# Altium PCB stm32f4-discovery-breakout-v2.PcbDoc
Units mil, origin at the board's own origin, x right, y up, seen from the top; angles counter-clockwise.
Board outline 1145.85 x 2951.23 mil, 2 copper layers (Top, Bottom); 5 components, 85 nets, 200 pads, 0 vias.
Unrouted connection lines stored in the file: 3.
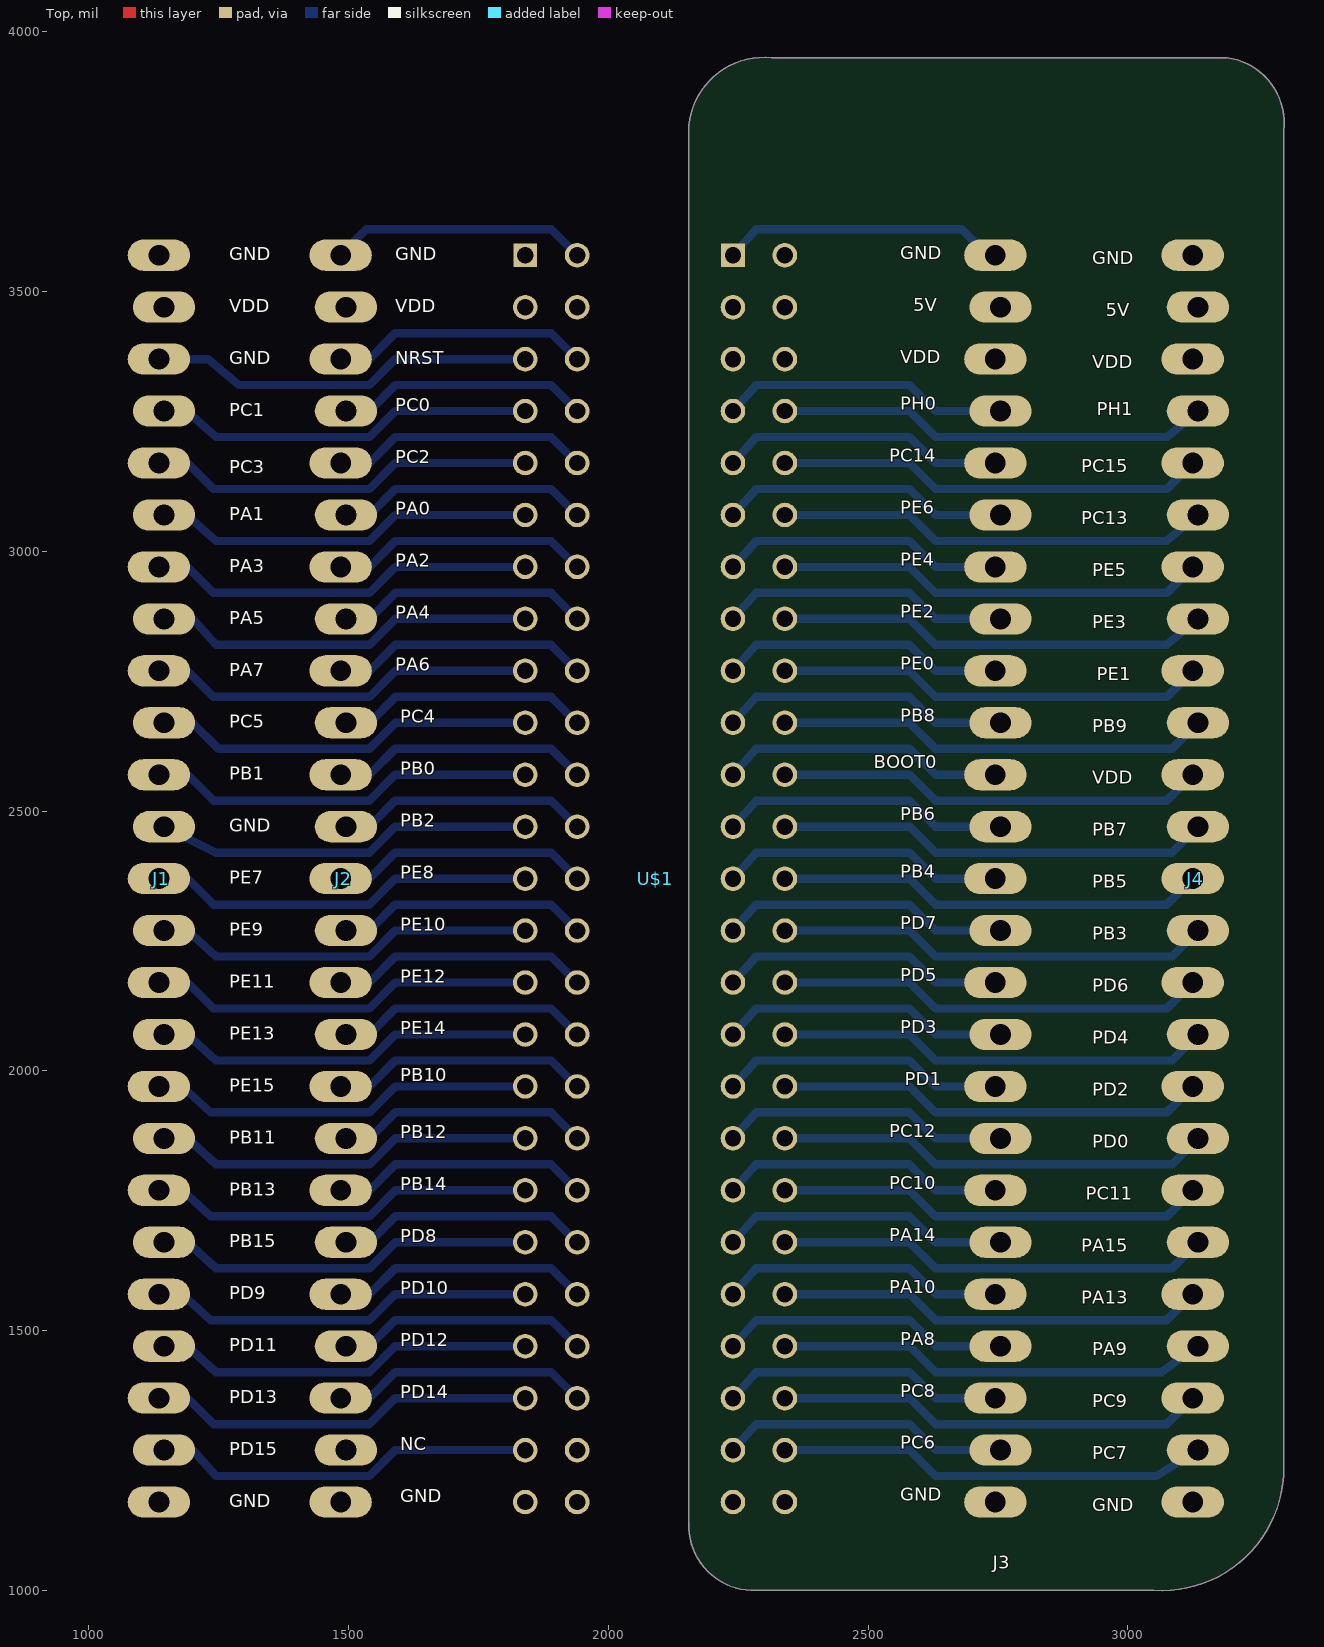
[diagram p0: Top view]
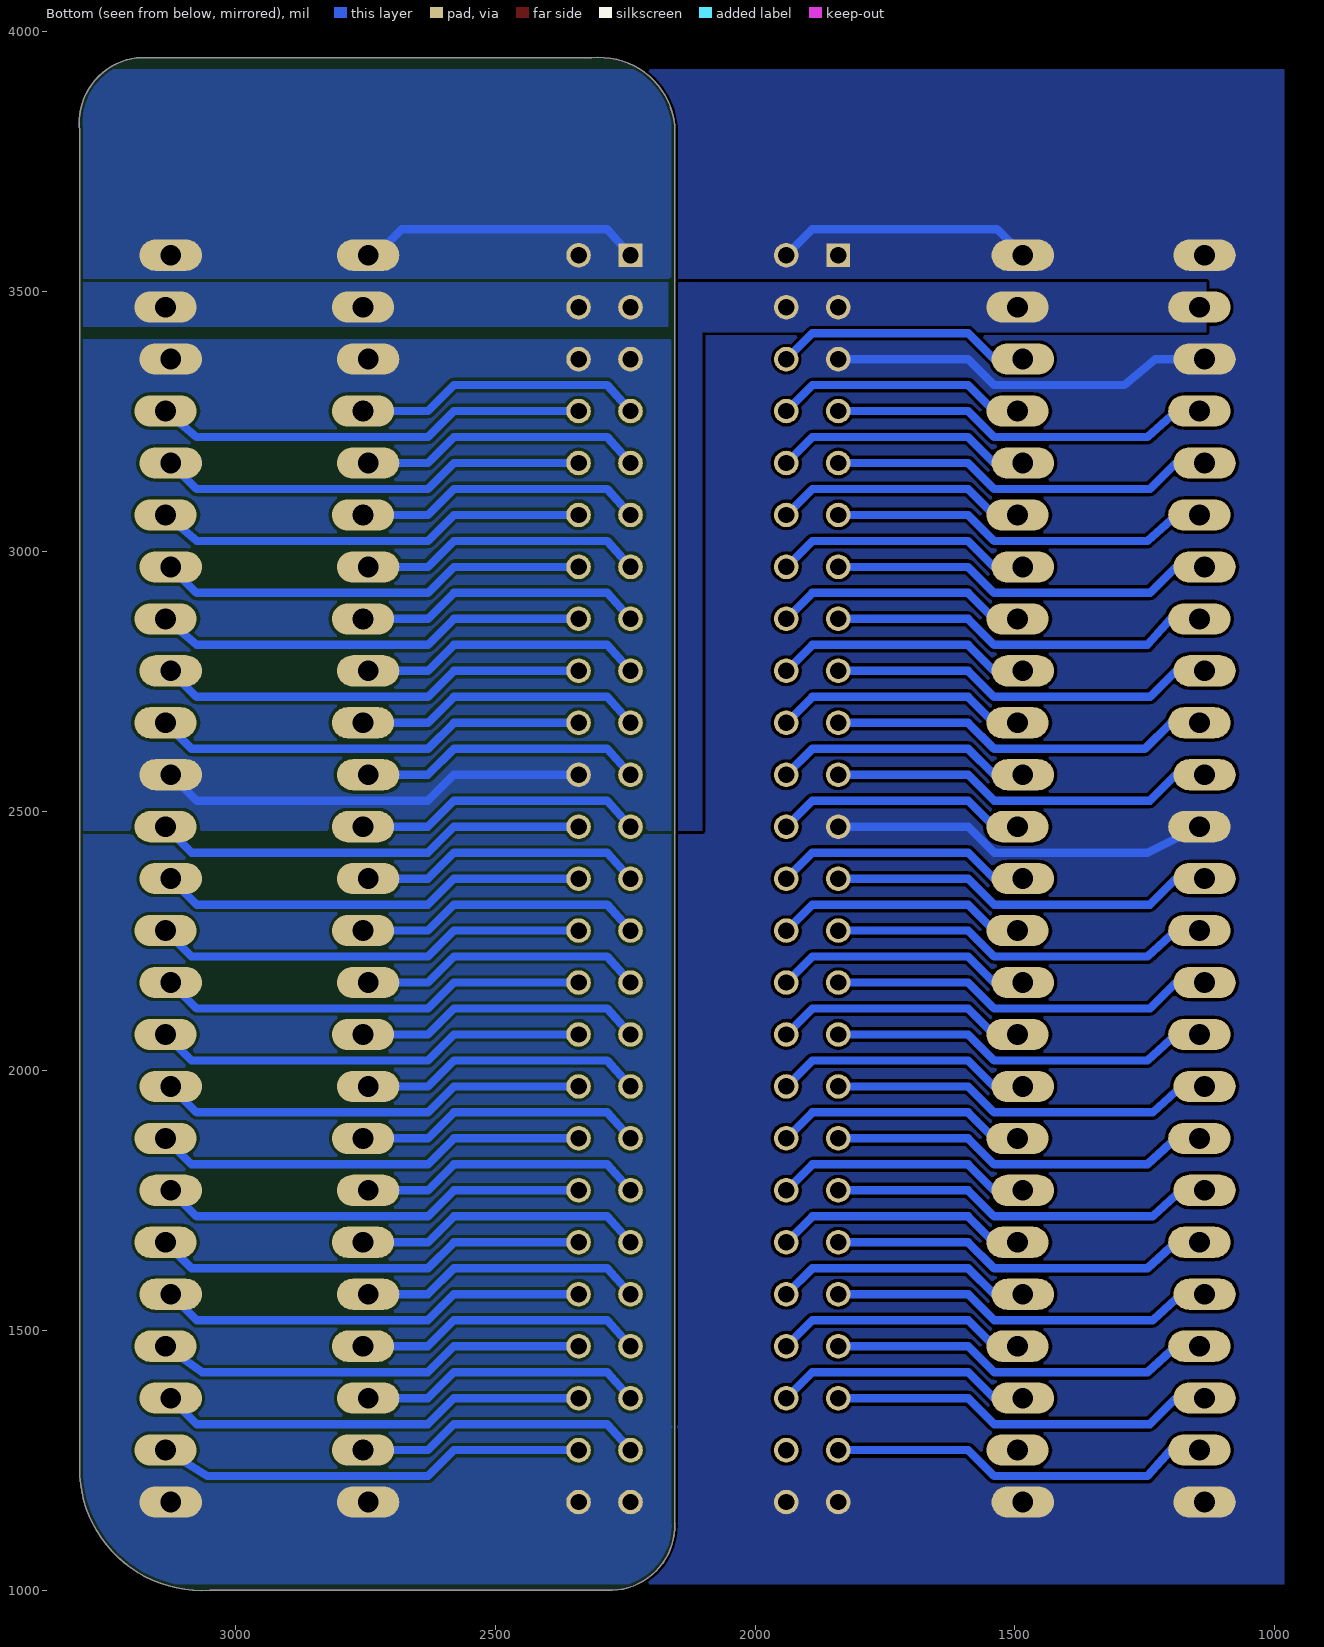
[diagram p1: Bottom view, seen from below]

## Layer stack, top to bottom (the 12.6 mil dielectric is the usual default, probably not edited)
Top Solder: solder mask 0.4, Solder Resist, Dk 3.5
Top: signal copper 1.4016
Dielectric 1: dielectric 12.6, FR-4, Dk 4.8
Bottom: signal copper 1.4016
Bottom Solder: solder mask 0.4, Solder Resist, Dk 3.5

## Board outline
2155,1320 2155,3820 cw(c2300,3805) 2315,3950 3190,3950 cw(c3175,3825) 3300,3810 3300,1220 cw(c3065,1235) 3050,1000 2275,1000 cw(c2280,1125) 2155,1130

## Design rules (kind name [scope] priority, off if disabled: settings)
Clearance "Clearance (Same Net)" [All] p1: gap=6 ignorepadtopadclearanceinfootprint=FALSE
Clearance [All] p2: gap=6 ignorepadtopadclearanceinfootprint=FALSE except(20: Arc-Poly Track-Poly SMDPad-Poly THPad-Poly Via-Poly Fill-Poly Poly-Poly Poly-Region Poly-Text Poly-Hole)
HoleSize [All] p1: absolutevalues=TRUE maxlimit=100000 minlimit=13 maxpercent=80.000 minpercent=20.000
HoleToHoleClearance mdDrill [All] p1: gap=6 allowstackedmicrovias=TRUE
PasteMaskExpansion mlMinCreamFrame [All] p1: expansion=0
PolygonConnect ThermalVias [IsVia] p1: connectstyle=Direct reliefconductorwidth=10 reliefentries=4 polygonreliefangle="90 Angle" airgapwidth=10
PolygonConnect [All] p2: connectstyle=Direct reliefconductorwidth=10 reliefentries=4 polygonreliefangle="90 Angle" airgapwidth=10
RoutingVias [All] p1: holewidth=13 width=27 viastyle="Through Hole" minholewidth=13 minwidth=27 maxholewidth=100 maxwidth=100
SolderMaskExpansion mlMinStopFrame [All] p1: expansion=3
Width [All] p1: maxlimit=10000 minlimit=6 preferedwidth=6
27 further rules are at their usual default settings.

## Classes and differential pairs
polygon class Isolate_20: Polygon_1_Net_GND Polygon_1_Net_VDD

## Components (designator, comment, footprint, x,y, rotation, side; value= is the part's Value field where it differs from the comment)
J1 "" 1X25_LOCK_LONGPADS 1140,1170 r90 top
J2 "" 1X25_LOCK_LONGPADS 1490,1170 r90 top
J3 "" 1X25_LOCK_LONGPADS 2750,1170 r90 top
J4 "" 1X25_LOCK_LONGPADS 3130,1170 r90 top
U$1 "" STM32F4-DISCOVERY 2940,2370 r0 top

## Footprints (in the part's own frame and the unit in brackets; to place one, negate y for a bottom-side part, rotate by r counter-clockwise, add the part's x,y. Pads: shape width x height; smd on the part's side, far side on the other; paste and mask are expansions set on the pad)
1X25_LOCK_LONGPADS [mil] "1X25_LOCK_LONGPADS"
  oval 60x120 / inner round 60 / far side oval 60x120 hole 40: 1(0,5) 2(100,-5) 3(200,5) 4(300,-5) 5(400,5) 6(500,-5) 7(600,5) 8(700,-5) 9(800,5) 10(900,-5) 11(1000,5) 12(1100,-5) 13(1200,5) 14(1300,-5) 15(1400,5) 16(1500,-5) 17(1600,5) 18(1700,-5) 19(1800,5) 20(1900,-5) 21(2000,5) 22(2100,-5) 23(2200,5) 24(2300,-5) 25(2400,5)
STM32F4-DISCOVERY [mil] "STM32F4-DISCOVERY"
  rect 45.75x45.75 / inner rect 60x60 / far side rect 45.75x45.75 hole 31.5: P$1(-1100,1200) P$51(-700,1200)
  round 47.25 / inner round 60 / far side round 47.25 hole 31.5: P$2(-1000,1200) P$3(-1100,1100) P$4(-1000,1100) P$5(-1100,1000) P$6(-1000,1000) P$7(-1100,900) P$8(-1000,900) P$9(-1100,800) P$10(-1000,800) P$11(-1100,700) P$12(-1000,700) P$13(-1100,600) P$14(-1000,600) P$15(-1100,500) P$16(-1000,500) P$17(-1100,400) P$18(-1000,400) P$19(-1100,300) P$20(-1000,300) P$21(-1100,200) P$22(-1000,200) P$23(-1100,100) P$24(-1000,100) P$25(-1100,0) P$26(-1000,0) P$27(-1100,-100) P$28(-1000,-100) P$29(-1100,-200) P$30(-1000,-200) P$31(-1100,-300) P$32(-1000,-300) P$33(-1100,-400) P$34(-1000,-400) P$35(-1100,-500) P$36(-1000,-500) P$37(-1100,-600) P$38(-1000,-600) P$39(-1100,-700) P$40(-1000,-700) P$41(-1100,-800) P$42(-1000,-800) P$43(-1100,-900) P$44(-1000,-900) P$45(-1100,-1000) P$46(-1000,-1000) P$47(-1100,-1100) P$48(-1000,-1100) P$49(-1100,-1200) P$50(-1000,-1200) P$52(-600,1200) P$53(-700,1100) P$54(-600,1100) P$55(-700,1000) P$56(-600,1000) P$57(-700,900) P$58(-600,900) P$59(-700,800) P$60(-600,800) P$61(-700,700) P$62(-600,700) P$63(-700,600) P$64(-600,600) P$65(-700,500) P$66(-600,500) P$67(-700,400) P$68(-600,400) P$69(-700,300) P$70(-600,300) P$71(-700,200) P$72(-600,200) P$73(-700,100) P$74(-600,100) P$75(-700,0) P$76(-600,0) P$77(-700,-100) P$78(-600,-100) P$79(-700,-200) P$80(-600,-200) P$81(-700,-300) P$82(-600,-300) P$83(-700,-400) P$84(-600,-400) P$85(-700,-500) P$86(-600,-500) P$87(-700,-600) P$88(-600,-600) P$89(-700,-700) P$90(-600,-700) P$91(-700,-800) P$92(-600,-800) P$93(-700,-900) P$94(-600,-900) P$95(-700,-1000) P$96(-600,-1000) P$97(-700,-1100) P$98(-600,-1100) P$99(-700,-1200) P$100(-600,-1200)

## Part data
J1 J2 J3 J4: library part 1X25_LOCK_LONGPADS
U$1: library part STM32F4-DISCOVERY

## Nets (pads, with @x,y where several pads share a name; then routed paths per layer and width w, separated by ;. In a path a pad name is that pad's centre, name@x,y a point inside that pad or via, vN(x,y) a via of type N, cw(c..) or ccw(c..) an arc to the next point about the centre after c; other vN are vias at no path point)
5V: J3.24 J4.24 U$1.P$53 U$1.P$54
BOOT0: J3.15 U$1.P$71 | length 548
  Bottom w16: U$1.P$71 2285,2620 2580,2620 2630,2570 J3.15
GND: J1.1 J1.14 J1.23 J1.25 J2.1 J2.25 J3.1 J3.25 J4.1 J4.25 U$1.P$1 U$1.P$2 U$1.P$5 U$1.P$23 U$1.P$49 U$1.P$50 U$1.P$51 U$1.P$52 U$1.P$99 U$1.P$100 | length 2515.7
  Bottom w16: J1.23 1230,3370 1290,3320 1540,3320 1590,3370 U$1.P$5 ; J1.14 1245,2420 1540,2420 1590,2470 U$1.P$23 ; J2.25 1535,3620 1890,3620 U$1.P$2 ; U$1.P$51 2285,3620 2680,3620 2730,3570 J3.25
NRST: J2.23 U$1.P$6 | length 496.4
  Bottom w16: J2.23 1540,3370 1590,3420 1890,3420 U$1.P$6
PA0: J2.20 U$1.P$12 | length 491.4
  Bottom w16: J2.20@1490,3070 J2.20 1540,3070 1590,3120 1890,3120 U$1.P$12
PA1: J1.20 U$1.P$11 | length 735.1
  Bottom w16: J1.20 1190,3070 1200,3060 1245,3020 1540,3020 1590,3070 U$1.P$11
PA2: J2.19 U$1.P$14 | length 496.4
  Bottom w16: J2.19 1540,2970 1590,3020 1890,3020 U$1.P$14
PA3: J1.19 U$1.P$13 | length 746.4
  Bottom w16: J1.19 1190,2970 1240,2920 1540,2920 1590,2970 U$1.P$13
PA4: J2.18 U$1.P$16 | length 491.4
  Bottom w16: J2.18@1490,2870 J2.18 1540,2870 1590,2920 1890,2920 U$1.P$16
PA5: J1.18 U$1.P$15 | length 738
  Bottom w16: J1.18 1200,2870 1245,2820 1540,2820 1590,2870 U$1.P$15
PA6: J2.17 U$1.P$18 | length 496.4
  Bottom w16: J2.17 1540,2770 1590,2820 1890,2820 U$1.P$18
PA7: J1.17 U$1.P$17 | length 746.4
  Bottom w16: J1.17 1190,2770 1240,2720 1540,2720 1590,2770 U$1.P$17
PA8: J3.4 U$1.P$93 | length 558
  Bottom w16: U$1.P$93 2285,1520 2580,1520 2630,1470 J3.4
PA9: J4.4 U$1.P$94 | length 831.7
  Bottom w16: U$1.P$94 2580,1470 2630,1420 3065,1420 J4.4
PA10: J3.5 U$1.P$91 | length 548
  Bottom w16: U$1.P$91 2285,1620 2580,1620 2630,1570 J3.5
PA13: J4.5 U$1.P$92 | length 826.4
  Bottom w16: U$1.P$92 2580,1570 2630,1520 3075,1520 J4.5
PA14: J3.6 U$1.P$89 | length 558
  Bottom w16: U$1.P$89 2285,1720 2580,1720 2630,1670 J3.6
PA15: J4.6 U$1.P$90 | length 836.4
  Bottom w16: U$1.P$90 2580,1670 2630,1620 3085,1620 J4.6
PB0: J2.15 U$1.P$22 | length 496.4
  Bottom w16: J2.15 1540,2570 1590,2620 1890,2620 U$1.P$22
PB1: J1.15 U$1.P$21 | length 746.4
  Bottom w16: J1.15 1190,2570 1240,2520 1540,2520 1590,2570 U$1.P$21
PB2: J2.14 U$1.P$24 | length 486.4
  Bottom w16: J2.14 1540,2470 1590,2520 1890,2520 U$1.P$24
PB3: J4.12 U$1.P$78 | length 836.4
  Bottom w16: U$1.P$78 2580,2270 2630,2220 3085,2220 J4.12
PB4: J3.13 U$1.P$75 | length 548
  Bottom w16: U$1.P$75 2285,2420 2580,2420 2630,2370 J3.13
PB5: J4.13 U$1.P$76 | length 826.4
  Bottom w16: U$1.P$76 2580,2370 2630,2320 3075,2320 J4.13
PB6: J3.14 U$1.P$73 | length 558
  Bottom w16: U$1.P$73 2285,2520 2580,2520 2630,2470 J3.14
PB7: J4.14 U$1.P$74 | length 836.4
  Bottom w16: U$1.P$74 2580,2470 2630,2420 3085,2420 J4.14
PB8: J3.16 U$1.P$69 | length 558
  Bottom w16: U$1.P$69 2285,2720 2580,2720 2630,2670 J3.16
PB9: J4.16 U$1.P$70 | length 836.4
  Bottom w16: U$1.P$70 2580,2670 2630,2620 3085,2620 J4.16
PB10: J2.9 U$1.P$34 | length 496.4
  Bottom w16: J2.9 1540,1970 1590,2020 1890,2020 U$1.P$34
PB11: J1.8 U$1.P$35 | length 735
  Bottom w16: J1.8 1190,1870 1245,1820 1540,1820 1590,1870 U$1.P$35
PB12: J2.8 U$1.P$36 | length 486.4
  Bottom w16: J2.8 1540,1870 1590,1920 1890,1920 U$1.P$36
PB13: J1.7 U$1.P$37 | length 745
  Bottom w16: J1.7 1180,1770 1235,1720 1540,1720 1590,1770 U$1.P$37
PB14: J2.7 U$1.P$38 | length 496.4
  Bottom w16: J2.7 1540,1770 1590,1820 1890,1820 U$1.P$38
PB15: J1.6 U$1.P$39 | length 735
  Bottom w16: J1.6 1190,1670 1245,1620 1540,1620 1590,1670 U$1.P$39
PC0: J2.22 U$1.P$8 | length 486.4
  Bottom w16: J2.22 1540,3270 1590,3320 1890,3320 U$1.P$8
PC1: J1.22 U$1.P$7 | length 735.1
  Bottom w16: J1.22 1190,3270 1200,3260 1245,3220 1540,3220 1590,3270 U$1.P$7
PC2: J2.21 U$1.P$10 | length 496.4
  Bottom w16: J2.21 1540,3170 1590,3220 1890,3220 U$1.P$10
PC3: J1.21 U$1.P$9 | length 746.4
  Bottom w16: J1.21 1190,3170 1240,3120 1540,3120 1590,3170 U$1.P$9
PC4: J2.16 U$1.P$20 | length 486.4
  Bottom w16: J2.16 1540,2670 1590,2720 1890,2720 U$1.P$20
PC5: J1.16 U$1.P$19 | length 736.4
  Bottom w16: J1.16 1200,2670 1250,2620 1540,2620 1590,2670 U$1.P$19
PC6: J3.2 U$1.P$97 | length 558
  Bottom w16: U$1.P$97 2285,1320 2580,1320 2630,1270 J3.2
PC7: J4.2 U$1.P$98 | length 830.1
  Bottom w16: U$1.P$98 2580,1270 2630,1220 3055,1220 J4.2
PC8: J3.3 U$1.P$95 | length 548
  Bottom w16: U$1.P$95 2285,1420 2580,1420 2630,1370 J3.3
PC9: J4.3 U$1.P$96 | length 826.4
  Bottom w16: U$1.P$96 2580,1370 2630,1320 3075,1320 J4.3
PC10: J3.7 U$1.P$87 | length 583
  Bottom w16: U$1.P$87 2285,1820 2580,1820 2630,1770 J3.7 J3.7@2780,1770
PC11: J4.7 U$1.P$88 | length 826.4
  Bottom w16: U$1.P$88 2580,1770 2630,1720 3075,1720 J4.7
PC12: J3.8 U$1.P$85 | length 558
  Bottom w16: U$1.P$85 2285,1920 2580,1920 2630,1870 J3.8
PC13: J4.20 U$1.P$62 | length 833.8
  Bottom w16: U$1.P$62 2580,3070 2630,3020 3075,3020 J4.20
PC14: J3.21 U$1.P$59 | length 548
  Bottom w16: U$1.P$59 2285,3220 2580,3220 2630,3170 J3.21
PC15: J4.21 U$1.P$60 | length 826.4
  Bottom w16: U$1.P$60 2580,3170 2630,3120 3075,3120 J4.21
PD0: J4.8 U$1.P$86 | length 836.4
  Bottom w16: U$1.P$86 2580,1870 2630,1820 3085,1820 J4.8
PD1: J3.9 U$1.P$83 | length 548
  Bottom w16: U$1.P$83 2285,2020 2580,2020 2630,1970 J3.9
PD2: J4.9 U$1.P$84 | length 826.4
  Bottom w16: U$1.P$84 2580,1970 2630,1920 3075,1920 J4.9
PD3: J3.10 U$1.P$81 | length 558
  Bottom w16: U$1.P$81 2285,2120 2580,2120 2630,2070 J3.10
PD4: J4.10 U$1.P$82 | length 836.4
  Bottom w16: U$1.P$82 2580,2070 2630,2020 3085,2020 J4.10
PD5: J3.11 U$1.P$79 | length 548
  Bottom w16: U$1.P$79 2285,2220 2580,2220 2630,2170 J3.11
PD6: J4.11 U$1.P$80 | length 826.4
  Bottom w16: U$1.P$80 2580,2170 2630,2120 3075,2120 J4.11
PD7: J3.12 U$1.P$77 | length 558
  Bottom w16: U$1.P$77 2285,2320 2580,2320 2630,2270 J3.12
PD8: J2.6 U$1.P$40 | length 486.4
  Bottom w16: J2.6 1540,1670 1590,1720 1890,1720 U$1.P$40
PD9: J1.5 U$1.P$41 | length 745
  Bottom w16: J1.5 1180,1570 1235,1520 1540,1520 1590,1570 U$1.P$41
PD10: J2.5 U$1.P$42 | length 496.4
  Bottom w16: J2.5 1540,1570 1590,1620 1890,1620 U$1.P$42
PD11: J1.4 U$1.P$43 | length 735
  Bottom w16: J1.4 1190,1470 1245,1420 1540,1420 1590,1470 U$1.P$43
PD12: J2.4 U$1.P$44 | length 486.4
  Bottom w16: J2.4 1540,1470 1590,1520 1890,1520 U$1.P$44
PD13: J1.3 U$1.P$45 | length 746.4
  Bottom w16: J1.3 1190,1370 1240,1320 1540,1320 1590,1370 U$1.P$45
PD14: J2.3 U$1.P$46 | length 496.4
  Bottom w16: J2.3 1540,1370 1590,1420 1890,1420 U$1.P$46
PD15: J1.2 U$1.P$47 | length 738
  Bottom w16: J1.2 1200,1270 1245,1220 1540,1220 1590,1270 U$1.P$47
PE0: J3.17 U$1.P$67 | length 548
  Bottom w16: U$1.P$67 2285,2820 2580,2820 2630,2770 J3.17
PE1: J4.17 U$1.P$68 | length 826.4
  Bottom w16: U$1.P$68 2580,2770 2630,2720 3075,2720 J4.17
PE2: J3.18 U$1.P$65 | length 558
  Bottom w16: U$1.P$65 2285,2920 2580,2920 2630,2870 J3.18
PE3: J4.18 U$1.P$66 | length 833.8
  Bottom w16: U$1.P$66 2580,2870 2630,2820 3075,2820 J4.18
PE4: J3.19 U$1.P$63 | length 548
  Bottom w16: U$1.P$63 2285,3020 2580,3020 2630,2970 J3.19
PE5: J4.19 U$1.P$64 | length 826.4
  Bottom w16: U$1.P$64 2580,2970 2630,2920 3075,2920 J4.19
PE6: J3.20 U$1.P$61 | length 558
  Bottom w16: U$1.P$61 2285,3120 2580,3120 2630,3070 J3.20
PE7: J1.13 U$1.P$25 | length 746.4
  Bottom w16: J1.13 1190,2370 1240,2320 1540,2320 1590,2370 U$1.P$25
PE8: J2.13 U$1.P$26 | length 496.4
  Bottom w16: J2.13 1540,2370 1590,2420 1890,2420 U$1.P$26
PE9: J1.12 U$1.P$27 | length 735
  Bottom w16: J1.12 1190,2270 1245,2220 1540,2220 1590,2270 U$1.P$27
PE10: J2.12 U$1.P$28 | length 486.4
  Bottom w16: J2.12 1540,2270 1590,2320 1890,2320 U$1.P$28
PE11: J1.11 U$1.P$29 | length 746.4
  Bottom w16: J1.11 1190,2170 1240,2120 1540,2120 1590,2170 U$1.P$29
PE12: J2.11 U$1.P$30 | length 496.4
  Bottom w16: J2.11 1540,2170 1590,2220 1890,2220 U$1.P$30
PE13: J1.10 U$1.P$31 | length 735
  Bottom w16: J1.10 1190,2070 1245,2020 1540,2020 1590,2070 U$1.P$31
PE14: J2.10 U$1.P$32 | length 486.4
  Bottom w16: J2.10 1540,2070 1590,2120 1890,2120 U$1.P$32
PE15: J1.9 U$1.P$33 | length 745
  Bottom w16: J1.9 1180,1970 1235,1920 1540,1920 1590,1970 U$1.P$33
PH0: J3.22 U$1.P$57 | length 558
  Bottom w16: U$1.P$57 2285,3320 2580,3320 2630,3270 J3.22
PH1: J4.22 U$1.P$58 | length 833.8
  Bottom w16: U$1.P$58 2580,3270 2630,3220 3075,3220 J4.22
VDD: J1.24 J2.24 J3.23 J4.15 J4.23 U$1.P$3 U$1.P$4 U$1.P$55 U$1.P$56 U$1.P$72 | length 826.4
  Bottom w16: U$1.P$72 2580,2570 2630,2520 3075,2520 J4.15
pads on no net: J2.2 U$1.P$48

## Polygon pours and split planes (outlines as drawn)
GND on Bottom "Polygon_1_Net_GND" (solid, remove dead copper, pour order 2): 982,3928 982,1012 3388,1012 3388,3928
5V on Bottom "Polygon_1_Net_5V" (solid, remove dead copper, pour order 1): 2167,3518 2167,3432 3358,3432 3358,3518
VDD on Bottom "Polygon_1_Net_VDD" (solid, remove dead copper, pour order 0): 2163,3408 3358,3408 3358,2462 2102,2462 2102,3422 1132,3422 1132,3518 2163,3518

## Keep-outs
Keep-Out Layer:
  lines w0: 2155,1310 2155,1130 ccw(c2280,1125) 2275,1000 3050,1000 ccw(c3065,1235) 3300,1220 3300,3810 ccw(c3175,3825) 3190,3950 2315,3950 ccw(c2300,3805) 2155,3820 2155,1320

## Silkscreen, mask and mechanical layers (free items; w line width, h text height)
Top Overlay:
  text "GND" at 2561.82,3562.15 h25.5
  text "GND" at 1270,3560 h25.5
  text "GND" at 1590,3560 h25.5
  text "GND" at 2931.82,3552.15 h25.5
  text "5V" at 2587.31,3462.15 h25.5
  text "VDD" at 1270,3460 h25.5
  text "VDD" at 1590,3460 h25.5
  text "5V" at 2957.31,3452.15 h25.5
  text "VDD" at 2561.82,3362.15 h25.5
  text "GND" at 1270,3360 h25.5
  text "NRST" at 1590,3360 h25.5
  text "VDD" at 2931.82,3352.15 h25.5
  text "PH0" at 2561.82,3272.15 h25.5
  text "PC0" at 1590,3270 h25.5
  text "PH1" at 2940.32,3262.15 h25.5
  text "PC1" at 1270,3260 h25.5
  text "PC14" at 2540.58,3172.15 h25.5
  text "PC2" at 1590,3170 h25.5
  text "PC15" at 2910.58,3152.15 h25.5
  text "PC3" at 1270,3150 h25.5
  text "PE6" at 2561.82,3072.15 h25.5
  text "PA0" at 1590,3070 h25.5
  text "PA1" at 1270,3060 h25.5
  text "PC13" at 2910.58,3052.15 h25.5
  text "PE4" at 2561.82,2972.15 h25.5
  text "PA2" at 1590,2970 h25.5
  text "PA3" at 1270,2960 h25.5
  text "PE5" at 2931.82,2952.15 h25.5
  text "PE2" at 2561.82,2872.15 h25.5
  text "PA4" at 1590,2870 h25.5
  text "PA5" at 1270,2860 h25.5
  text "PE3" at 2931.82,2852.15 h25.5
  text "PE0" at 2561.82,2772.15 h25.5
  text "PA6" at 1590,2770 h25.5
  text "PA7" at 1270,2760 h25.5
  text "PE1" at 2940.32,2752.15 h25.5
  text "PB8" at 2561.82,2672.15 h25.5
  text "PC4" at 1600,2670 h25.5
  text "PC5" at 1270,2660 h25.5
  text "PB9" at 2931.82,2652.15 h25.5
  text "BOOT0" at 2510.84,2582.15 h25.5
  text "PB0" at 1600,2570 h25.5
  text "PB1" at 1270,2560 h25.5
  text "VDD" at 2931.82,2552.15 h25.5
  text "PB6" at 2561.82,2482.15 h25.5
  text "PB2" at 1600,2470 h25.5
  text "GND" at 1270,2460 h25.5
  text "PB7" at 2931.82,2452.15 h25.5
  text "PB4" at 2561.82,2372.15 h25.5
  text "PE8" at 1600,2370 h25.5
  text "PE7" at 1270,2360 h25.5
  text "PB5" at 2931.82,2352.15 h25.5
  text "PD7" at 2561.82,2272.15 h25.5
  text "PE10" at 1600,2270 h25.5
  text "PE9" at 1270,2260 h25.5
  text "PB3" at 2931.82,2252.15 h25.5
  text "PD5" at 2561.82,2172.15 h25.5
  text "PE12" at 1600,2170 h25.5
  text "PE11" at 1270,2160 h25.5
  text "PD6" at 2931.82,2152.15 h25.5
  text "PD3" at 2561.82,2072.15 h25.5
  text "PE14" at 1600,2070 h25.5
  text "PE13" at 1270,2060 h25.5
  text "PD4" at 2931.82,2052.15 h25.5
  text "PB10" at 1600,1980 h25.5
  text "PD1" at 2570.32,1972.15 h25.5
  text "PE15" at 1270,1960 h25.5
  text "PD2" at 2931.82,1952.15 h25.5
  text "PC12" at 2540.58,1872.15 h25.5
  text "PB12" at 1600,1870 h25.5
  text "PB11" at 1270,1860 h25.5
  text "PD0" at 2931.82,1852.15 h25.5
  text "PC10" at 2540.58,1772.15 h25.5
  text "PB14" at 1600,1770 h25.5
  text "PB13" at 1270,1760 h25.5
  text "PC11" at 2919.08,1752.15 h25.5
  text "PA14" at 2540.58,1672.15 h25.5
  text "PD8" at 1600,1670 h25.5
  text "PB15" at 1270,1660 h25.5
  text "PA15" at 2910.58,1652.15 h25.5
  text "PA10" at 2540.58,1572.15 h25.5
  text "PD10" at 1600,1570 h25.5
  text "PD9" at 1270,1560 h25.5
  text "PA13" at 2910.58,1552.15 h25.5
  text "PA8" at 2561.82,1472.15 h25.5
  text "PD12" at 1600,1470 h25.5
  text "PD11" at 1270,1460 h25.5
  text "PA9" at 2931.82,1452.15 h25.5
  text "PC8" at 2561.82,1372.15 h25.5
  text "PD14" at 1600,1370 h25.5
  text "PD13" at 1270,1360 h25.5
  text "PC9" at 2931.82,1352.15 h25.5
  text "PC6" at 2561.82,1272.15 h25.5
  text "NC" at 1600,1270 h25.5
  text "PD15" at 1270,1260 h25.5
  text "PC7" at 2931.82,1252.15 h25.5
  text "GND" at 2561.82,1172.15 h25.5
  text "GND" at 1600,1170 h25.5
  text "GND" at 1270,1160 h25.5
  text "GND" at 2931.82,1152.15 h25.5
Dimension:
  lines w0: 1000,1310 1000,1130 ccw(c1125,1125) 1120,1000 1900,1000 ccw(c1905,1125) 2030,1120 2030,3810 ccw(c1905,3825) 1920,3950 1160,3950 ccw(c1145,3805) 1000,3820 1000,1320 ; 2155,1310 2155,1130 ccw(c2280,1125) 2275,1000 3050,1000 ccw(c3065,1235) 3300,1220 3300,3810 ccw(c3175,3825) 3190,3950 2315,3950 ccw(c2300,3805) 2155,3820 2155,1320
Unrouted:
  lines w0: 1940,1170 2240,1170 ; 1940,3470 2240,3370 ; 1940,3570 2240,3570
Top Assembly:
  text "Wickerbox Electronics" at 1090,3830 h42.5
  text "STM32F4-DISCOVERY" at 2285,3830 h42.5
  text "jeh.wicker@gmail.com" at 1090,3760 h34
  text "Breakout Board v2" at 2285,3760 h42.5
  text "2 May 2015" at 1090,3690 h25.5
